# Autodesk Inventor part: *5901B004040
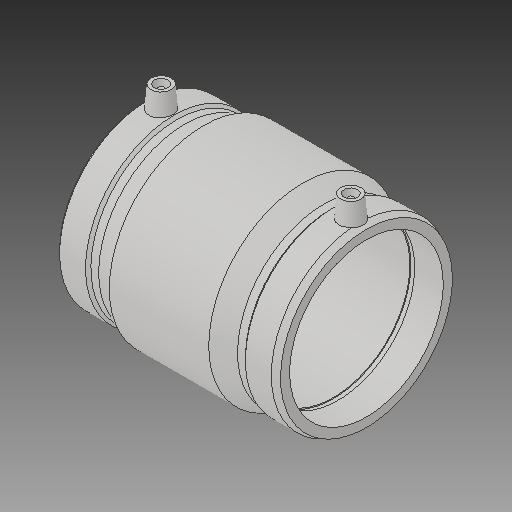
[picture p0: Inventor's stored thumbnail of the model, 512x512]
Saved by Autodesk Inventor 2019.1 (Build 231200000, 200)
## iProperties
Created: 2017-06
Part Number: *5901B004040
Material: Generic
Description: PLASSON IPS COUPLER 4''
Document SubType Name: Modeling
Designer: KIM
Mass: 8622.19 g
Surface Area: 6772.47 cm^2
Volume: 8622.19 cm^3
Density: 1 g/cm^3
Appearance: Default
Author: KIM
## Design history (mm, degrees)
derived "5901B.ipt"
feature "Solid1::5901B.ipt"
tag "TaggingFeature1"
body "Solid1"
other parameters: "d0" = 164.084, "d1" = 114.1, "d2" = 139.954, "d3" = 80.01, "d4" = 41.021, "d5" = 125.9586, "d6" = 91.28, "d7" = 114.1, "d8" = 168 deg, "d10" = 32.004, "d11" = 10.668, "d13" = 164.084, "d14" = 17.6296, "d18" = 114.1, "d19" = 3.52592, "d20" = 168 deg, "d22" = 131.55676, "d23" = 139.954, "d24" = 127.61006, "d25" = 135 deg, "d26" = 73.8378, "d27" = 135 deg, "d29" = 81.026, "d30" = 15, "d31" = 57.4294, "d34" = 5 deg, "d35" = 15, "d39" = 5 deg, "d41" = 4, "d42" = 14, "d43" = 0, "d45" = 4, "d46" = 14, "d47" = 0, "d48" = 3, "d49" = 0, "d50" = 3, "d51" = 0, "d52" = 23.2029, "d53" = 5.80072, "d55" = 80.01, "d_" = 114.1, "L_" = 164.084, "L_1" = 80.01, "D_" = 139.954, "A_" = 81.026, "d_2" = 12, "B_" = 81.026
